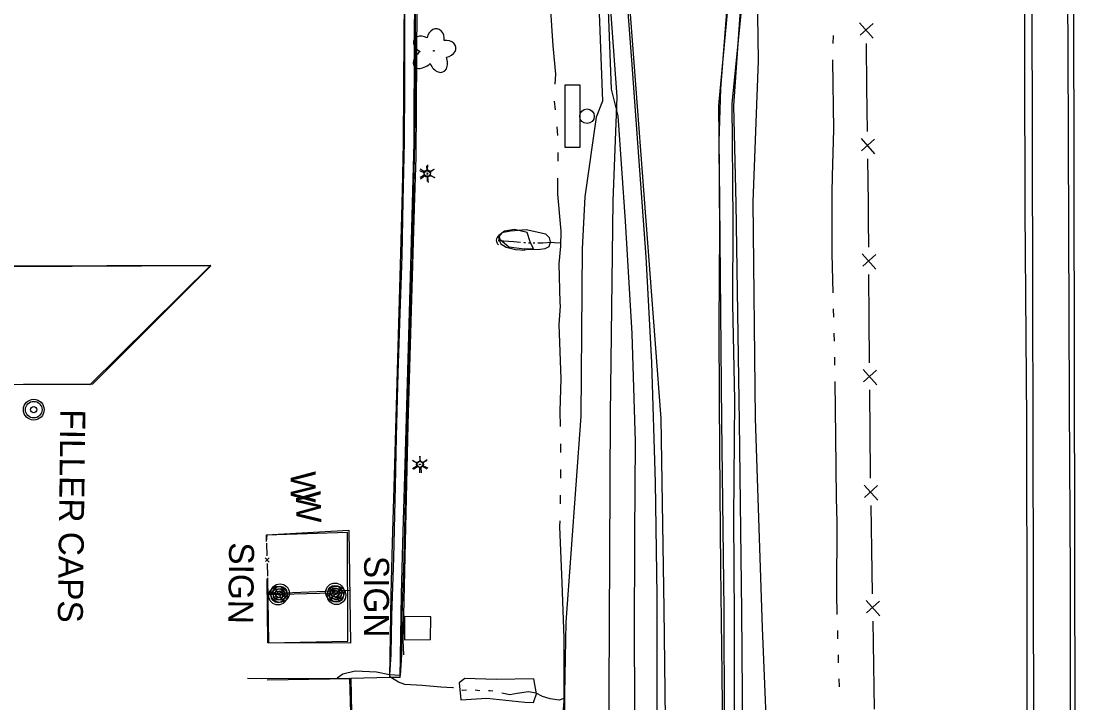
# Model space of a CAD drawing. Extents: x 588843 to 2552415, y 180129 to 269402.
# Drawn here: x 593696.8 to 593951.8, y 185185.1 to 185348.9 of the extents above; entities that cross this region are included whole.
import ezdxf

# ---------------------------------------------------------------- set-up
doc = ezdxf.new("R2010")
doc.units = 0
for name, color, linetype in [('Default', 7, 'Continuous'), ('E_BLD', 7, 'Continuous'), ('E_BLD_HvyDash', 7, 'Continuous'), ('E_DRN', 7, 'Continuous'), ('E_DRN_RipRap', 7, 'Continuous'), ('E_DWY', 7, 'Continuous'), ('E_FEN_P', 7, 'Continuous'), ('E_LAND_Vegetation', 7, 'Continuous'), ('E_LTG', 7, 'Continuous'), ('E_MISCPROP', 7, 'Continuous'), ('E_MISCPROP_Text', 7, 'Continuous'), ('E_RDWY', 7, 'Continuous'), ('E_RDWY_AsphConc', 7, 'Continuous'), ('E_RDWY_BarrierConc', 7, 'Continuous'), ('E_RDWY_C_and_G', 7, 'Continuous'), ('E_RDWY_Gravel', 7, 'Continuous'), ('E_RDWY_PavtEdge', 7, 'Continuous'), ('E_SGN', 7, 'Continuous'), ('E_SGN_Text', 7, 'Continuous'), ('E_STRUCT', 7, 'Continuous'), ('E_WAL', 7, 'Continuous'), ('E_WAL_Text', 7, 'Continuous'), ('E_WTR_P', 7, 'Continuous'), ('P_RDWY_BarrierConc', 7, 'Continuous'), ('P_RDWY_ShldPaved', 7, 'Continuous')]:
    doc.layers.add(name, color=color, linetype=linetype)

# ---------------------------------------------------------------- blocks, each defined once
blk = doc.blocks.new('FILO')
at = {"layer": 'E_MISCPROP'}
for radius in [5, 4, 1.5]:
    blk.add_circle((0, 0), radius, dxfattribs=at)
blk = doc.blocks.new('FILT')
at = {"layer": 'E_MISCPROP_Text'}
blk.add_text('FILLER CAPS', height=12, dxfattribs=at).set_placement((12, -4))
blk = doc.blocks.new('POLE')
at = {"layer": 'Default'}
for radius in [4.46, 3.35, 2.23, 1.12]:
    blk.add_circle((0, 0), radius, dxfattribs=at)
blk = doc.blocks.new('SIGN')
at = {"layer": 'Default'}
blk.add_text('SIGN', height=12, dxfattribs=at).set_placement((-18.55, -6))
blk = doc.blocks.new('LPOL')
at = {"layer": 'Default'}
for p, q in [((-4, 0), (-1.5, 0)), ((-0.75, 1.3), (-2, 3.46)), ((0.75, 1.3), (2, 3.46)), ((1.5, 0), (4, 0)), ((-2, -3.46), (-0.75, -1.3)), ((2, -3.46), (0.75, -1.3))]:
    blk.add_line(p, q, dxfattribs=at)
for radius in [1.5, 1.5, 1.5, 0.125]:
    blk.add_circle((0, 0), radius, dxfattribs=at)
blk = doc.blocks.new('W_61')
at = {"layer": 'E_WAL_Text'}
blk.add_text('W', height=12, dxfattribs=at).set_placement((-4.46, -6))
blk = doc.blocks.new('SGN_1')
at = {"layer": 'Default'}
blk.add_lwpolyline([(-3.5, -15), (-10.5, -15), (-10.5, 15), (-3.5, 15)], close=True, dxfattribs=at)
blk.add_circle((0, 0), 3.5, dxfattribs=at)
blk = doc.blocks.new('CULV2_4')
at = {"layer": 'E_DRN'}
blk.add_arc((65, 48), 80.7, 216.8699, 323.1301, dxfattribs=at)
blk = doc.blocks.new('POLE_3')
at = {"layer": 'E_MISCPROP'}
for radius in [14.6, 11, 7.32, 3.66]:
    blk.add_circle((0, 0), radius, dxfattribs=at)
blk = doc.blocks.new('LPOL_4')
at = {"layer": 'E_LTG'}
for p, q in [((-13.1, 0), (-4.9, 0)), ((-2.5, 4.3), (-6.6, 11.4)), ((2.5, 4.3), (6.6, 11.4)), ((4.9, 0), (13.1, 0)), ((-6.6, -11.4), (-2.5, -4.3)), ((6.6, -11.4), (2.5, -4.3))]:
    blk.add_line(p, q, dxfattribs=at)
for radius in [4.92, 4.92, 4.92, 0.41]:
    blk.add_circle((0, 0), radius, dxfattribs=at)
blk = doc.blocks.new('SIGN_3')
at = {"layer": 'E_SGN'}
blk.add_text('SIGN', height=39.37, dxfattribs=at).set_placement((-56.1, -19.7))
blk = doc.blocks.new('W_8_1')
at = {"layer": 'E_WAL_Text'}
blk.add_text('W', height=39.4, dxfattribs=at).set_placement((-14.6, -19.7))
blk = doc.blocks.new('DTRE_4')
at = {"layer": 'E_LAND_Vegetation'}
blk.add_circle((-0.6, 0), 0.601, dxfattribs=at)
for centre, major_axis, ratio in [((-6.1, 17.5), (4.5, -16.3), 0.782863), ((13.3, 9), (-17.3, -9.6), 0.691916), ((-19.3, 0.5), (16.2, -0.4), 0.832022), ((-8.2, -17.2), (5.9, 15.9), 0.716896), ((11.6, -12.2), (-16.4, 15), 0.560249)]:
    blk.add_ellipse(centre, major_axis=major_axis, ratio=ratio, start_param=1.570796, end_param=4.712389, dxfattribs=at)

msp = doc.modelspace()

# ---------------------------------------------------------------- linework, layer by layer
at = {"layer": 'E_BLD'}
msp.add_lwpolyline([(593595.41, 185342.82), (593542.04, 185289.64), (593742.37, 185290.28), (593713.31, 185261.53), (593514.99, 185261.87), (593447.83, 185195.35), (593433.78, 185195.34), (593433.67, 185288.83), (593458.13, 185312.89)], dxfattribs=at)
at = {"layer": 'E_BLD_HvyDash'}
msp.add_lwpolyline([(593513.7, 185260.82), (593714.03, 185261.73), (593742.37, 185290.1), (593542.12, 185289.15)], dxfattribs=at)
at = {"layer": 'E_DRN_RipRap'}
for points in [[(593818.43, 185298.09), (593815.41, 185298.81), (593812.98, 185298.45), (593811.59, 185297.38), (593811.88, 185296.54), (593814.07, 185294.67), (593817.72, 185294.22), (593819.99, 185294.22), (593819.17, 185295.85)], [(593820.03, 185190.89), (593810.98, 185190.77), (593803.43, 185190.94), (593802.1, 185189.91), (593802.48, 185185.86), (593808.76, 185186.28), (593817.87, 185185.31), (593819.94, 185185.2), (593820.71, 185187.29)]]:
    msp.add_lwpolyline(points, close=True, dxfattribs=at)
msp.add_lwpolyline([(593818.26, 185294.01), (593821.56, 185294.11), (593822.78, 185294.26), (593823.7, 185294.75), (593824.08, 185295.87), (593823.81, 185296.87), (593822.93, 185297.69), (593818.23, 185298.77), (593814.42, 185298.47), (593812.35, 185298.05), (593811.64, 185297.19), (593811.65, 185296.37), (593812.12, 185295.37), (593813.38, 185294.59), (593815.66, 185294.02), (593817.94, 185293.91)], dxfattribs=at)
at = {"layer": 'E_DWY'}
for points in [[(593779.28, 185414.41), (593780.64, 185411.67), (593783.45, 185404.25), (593785.68, 185397.13), (593787.43, 185390.2), (593788.2, 185384.9), (593788.79, 185378.59), (593788.96, 185370.88), (593789.05, 185361.06), (593788.98, 185348.55), (593788.98, 185333.57), (593788.87, 185319.82), (593788.56, 185305.76), (593788.27, 185292.48), (593787.8, 185278.7), (593787.36, 185264.28), (593786.97, 185249.03), (593786.71, 185237.17), (593786.32, 185219.98), (593785.83, 185206.1), (593785.7, 185196.77), (593785.38, 185191.85)], [(593781.51, 185415.53), (593782.94, 185412.67), (593785.82, 185405.07), (593788.08, 185397.81), (593789.89, 185390.69), (593790.68, 185385.2), (593791.29, 185378.74), (593791.46, 185370.92), (593791.55, 185361.07), (593791.48, 185348.55), (593791.48, 185333.56), (593791.37, 185319.78), (593791.06, 185305.7), (593790.76, 185292.41), (593790.29, 185278.61), (593789.86, 185264.21), (593789.47, 185248.97), (593789.21, 185237.11), (593788.82, 185219.91), (593788.33, 185206.04), (593788.2, 185196.68), (593787.88, 185191.69)], [(593791.37, 185345.7), (593791.5, 185360.24), (593791.42, 185372.16), (593790.98, 185381.83), (593790.26, 185388.49), (593789.29, 185392.53), (593787.06, 185400.28), (593783.01, 185411.71)], [(593788.87, 185345.72), (593789, 185360.24), (593788.92, 185372.09), (593788.49, 185381.64), (593787.79, 185388.06), (593786.87, 185391.89), (593784.68, 185399.51), (593780.65, 185410.88)], [(593785.39, 185191.25), (593785.75, 185211.18), (593786.05, 185223.58), (593786.54, 185239.7), (593787.08, 185259.3), (593787.56, 185276.23), (593788.06, 185293.13), (593788.48, 185308.13), (593788.74, 185319.7), (593788.87, 185345.72)], [(593787.89, 185191.21), (593788.25, 185211.13), (593788.55, 185223.52), (593789.04, 185239.63), (593789.58, 185259.23), (593790.06, 185276.16), (593790.56, 185293.06), (593790.98, 185308.07), (593791.24, 185319.67), (593791.37, 185345.7)], [(593787.88, 185191.69), (593785.38, 185191.85), (593782.22, 185192.52), (593777.11, 185192.74), (593774.09, 185191.99), (593772.73, 185191.04)], [(593787.89, 185191.21), (593785.39, 185191.25), (593776.03, 185190.97)]]:
    msp.add_lwpolyline(points, dxfattribs=at)
at = {"layer": 'E_FEN_P'}
for p, q in [((593898.37, 185348.46), (593901.63, 185344.81)), ((593901.58, 185348.33), (593898.47, 185345.52)), ((593898.71, 185320.71), (593901.97, 185317.06)), ((593901.92, 185320.58), (593898.81, 185317.76)), ((593899.01, 185292.96), (593902.25, 185289.29)), ((593902.23, 185292.82), (593899.1, 185290.01)), ((593899.22, 185265.21), (593902.46, 185261.54)), ((593902.43, 185265.06), (593899.3, 185262.26)), ((593899.45, 185237.44), (593902.73, 185233.8)), ((593902.67, 185237.32), (593899.57, 185234.49)), ((593755.48, 185219.96), (593756.43, 185218.94)), ((593756.4, 185219.94), (593755.53, 185219.12)), ((593899.93, 185209.68), (593903.21, 185206.05)), ((593903.15, 185209.57), (593900.05, 185206.74))]:
    msp.add_line(p, q, dxfattribs=at)
for points in [[(593899.91, 185343.55), (593900.04, 185332.95)], [(593900.04, 185332.95), (593900.17, 185322.36)], [(593900.25, 185315.8), (593900.38, 185305.2)], [(593900.38, 185305.2), (593900.43, 185301.11), (593900.48, 185294.6)], [(593900.53, 185288.04), (593900.61, 185277.44)], [(593900.61, 185277.44), (593900.69, 185266.85)], [(593900.74, 185260.29), (593900.82, 185249.69)], [(593900.82, 185249.69), (593900.89, 185240.29), (593900.91, 185239.09)], [(593901.02, 185232.53), (593901.2, 185221.94)], [(593755.81, 185223.45), (593755.89, 185220.44)], [(593901.2, 185221.94), (593901.39, 185211.34)], [(593755.95, 185218.57), (593756.03, 185215.56)], [(593901.5, 185204.78), (593901.68, 185194.19)], [(593901.68, 185194.19), (593901.86, 185183.59)]]:
    msp.add_lwpolyline(points, dxfattribs=at)
at = {"layer": 'E_RDWY'}
for points in [[(593875.84, 185453.5), (593875.18, 185444.55), (593873.42, 185426.77), (593871.63, 185407.61), (593869.74, 185387.1), (593868.31, 185371.28), (593866.46, 185352.19), (593864.94, 185332.65), (593864.52, 185319.97), (593864.65, 185298.49), (593864.53, 185275.87), (593864.59, 185257.56), (593864.77, 185235.68), (593864.91, 185217.64), (593865.21, 185192.03), (593865.51, 185169.15)], [(593883.34, 184797.63), (593880.29, 184822.58), (593876.81, 184852.9), (593873.76, 184879.56), (593870.15, 184910.6), (593867.01, 184938.51), (593863.39, 184971.22), (593860.52, 184996.66), (593857.95, 185023.1), (593855.61, 185048.62), (593852.95, 185083.15), (593851.06, 185119.17), (593850.2, 185152.54), (593849.72, 185184.93), (593849.66, 185210.92), (593849.31, 185238.05), (593848.37, 185266.91), (593847.03, 185292.29), (593845.07, 185319.69), (593843.62, 185339.55), (593841.62, 185365.79), (593839.25, 185395.75), (593838.48, 185404.83), (593836.91, 185426.06)]]:
    msp.add_lwpolyline(points, dxfattribs=at)
at = {"layer": 'E_RDWY_AsphConc'}
for points in [[(593880.44, 185453.26), (593877.09, 185432.82), (593874.68, 185401.65), (593869.68, 185351.53), (593868.04, 185328.52), (593868.59, 185305.06), (593869.44, 185252.63), (593869.98, 185207.15), (593870.24, 185177.47), (593870.68, 185147.16), (593871.02, 185130.16)], [(593835.51, 185420.49), (593834.36, 185418.93), (593835.27, 185400.95), (593838.25, 185354.97), (593839.96, 185330.69), (593839.05, 185305.69), (593838.39, 185254.46), (593838.17, 185204.09), (593837.95, 185155.65), (593837.92, 185121.35)]]:
    msp.add_lwpolyline(points, dxfattribs=at)
msp.add_lwpolyline([(593788.95, 185200.24), (593795.22, 185200.33), (593795.26, 185205.82), (593788.92, 185205.9)], close=True, dxfattribs=at)
at = {"layer": 'E_RDWY_BarrierConc'}
msp.add_lwpolyline([(593937.96, 185372.16), (593938.03, 185339.45), (593938.08, 185303.3), (593938.5, 185252.99), (593938.55, 185202.16), (593938.47, 185154.12), (593938.23, 185123.59), (593938.78, 185094.92), (593938.68, 185047.47)], dxfattribs=at)
at = {"layer": 'E_RDWY_C_and_G'}
msp.add_lwpolyline([(593788.78, 185196.64), (593788.64, 185200.13), (593788.81, 185206.13), (593789.8, 185251.96), (593791.36, 185304.06), (593791.76, 185316.22), (593792.01, 185352.33), (593791.93, 185366.51), (593791.98, 185372.66), (593791.74, 185378.81), (593791.74, 185378.81), (593791.28, 185384.15), (593790.58, 185389.46), (593790.58, 185389.46)], dxfattribs=at)
at = {"layer": 'E_RDWY_Gravel'}
for points in [[(593868.28, 185183.24), (593868.29, 185205.46), (593868.14, 185229.51), (593868.36, 185257.81), (593867.92, 185280.99), (593867.98, 185300.88), (593867.76, 185329.05), (593870.2, 185354), (593873.03, 185383.38), (593875.37, 185421.39), (593876.83, 185433.85), (593880.22, 185453.87)], [(593880.55, 185453.99), (593880.27, 185436.18), (593879.73, 185413.27), (593873.51, 185372.17), (593873.98, 185339.4), (593872.71, 185305.48), (593873.23, 185253.41), (593874.93, 185203.22), (593876.95, 185154.58), (593875.43, 185130.24)], [(593844.4, 185173.99), (593844.28, 185200.35), (593844.34, 185225.47), (593844.46, 185247.8), (593843.7, 185273.84), (593842.1, 185300.87), (593840.28, 185326.16), (593838.73, 185332.58), (593837.75, 185357.97), (593836.54, 185384.48), (593835.33, 185404.73), (593834.59, 185417.58), (593834.58, 185426.2)], [(593835.27, 185400.95), (593834.53, 185396.47), (593834.76, 185386.56), (593835.08, 185373.51), (593835.55, 185355.16), (593836.58, 185329.7), (593834.99, 185325.81), (593832.31, 185306.73), (593831.63, 185294.22), (593831.36, 185253.97), (593827.7, 185204.47), (593827.4, 185187.18), (593827.61, 185159.5), (593827.62, 185153.75), (593830.2, 185149.6), (593826.76, 185143.39), (593825.88, 185131.68), (593828.3, 185120.29), (593826.54, 185087.76), (593828.55, 185057.9)]]:
    msp.add_lwpolyline(points, dxfattribs=at)
at = {"layer": 'E_RDWY_PavtEdge'}
for points in [[(593875.85, 185453.59), (593873.92, 185432.86), (593870.99, 185400.68), (593866.59, 185351.79), (593864.42, 185328.6), (593864.71, 185305.3), (593865.19, 185252.78), (593865.69, 185207.57), (593865.81, 185180.99), (593866.2, 185154.42), (593866.2, 185154.42), (593866.82, 185130.11), (593866.82, 185130.11)], [(593839.4, 185400.62), (593842.88, 185354.87), (593846.48, 185307.23), (593850.58, 185253.42), (593851.31, 185207.69), (593851.9, 185154.74), (593851.9, 185154.74), (593852.41, 185121.99), (593852.41, 185121.99), (593853.62, 185093.61), (593853.62, 185093.61), (593854.67, 185076.65), (593855.94, 185059.71), (593855.94, 185059.71)]]:
    msp.add_lwpolyline(points, dxfattribs=at)
at = {"layer": 'E_SGN'}
msp.add_line((593756.39, 185211.19), (593774.53, 185211.66), dxfattribs=at)
msp.add_lwpolyline([(593756.14, 185211.36), (593775.77, 185212.17)], dxfattribs=at)
at = {"layer": 'E_STRUCT'}
msp.add_lwpolyline([(593949.5, 184809.8), (593949.49, 184844.07), (593949.38, 184874.99), (593949.34, 184910.76), (593949.25, 184952.33), (593949.24, 184977.34), (593949.2, 185005.39), (593949.13, 185032.79), (593948.99, 185077.15), (593948.89, 185110.83), (593948.85, 185154.41), (593949.04, 185179.37), (593949.06, 185215.53), (593948.81, 185257.23), (593948.62, 185298.71), (593948.49, 185342.33), (593948.21, 185388.66), (593948.33, 185405.71), (593947.89, 185415.89)], dxfattribs=at)
at = {"layer": 'E_WAL'}
for points in [[(593756.04, 185215.19), (593756.27, 185199.52), (593775.34, 185199.92), (593775.21, 185226.04), (593755.86, 185225.41), (593755.72, 185223.85)], [(593755.78, 185224.17), (593755.77, 185225.51), (593775.57, 185226.58), (593775.97, 185199.5), (593756.08, 185199.52), (593755.96, 185214.88)], [(593751.17, 185191.06), (593754.62, 185190.99), (593775.72, 185191.05), (593776.46, 185166.13), (593756.49, 185166)], [(593755.91, 185190.69), (593776.03, 185190.97), (593776.5, 185166.35), (593756.58, 185166.17)]]:
    msp.add_lwpolyline(points, dxfattribs=at)
at = {"layer": 'E_WTR_P'}
for points in [[(593823.71, 185363.59), (593823.68, 185362.86), (593823.95, 185352.65), (593824.62, 185342.95), (593825.23, 185336.17), (593825.06, 185333.77)], [(593891.98, 185345.44), (593891.92, 185343.5)], [(593891.81, 185339.64), (593891.8, 185339.36), (593892.06, 185322.9), (593891.79, 185311.63)], [(593824.94, 185329.66), (593825.14, 185327.61)], [(593825.54, 185323.51), (593825.74, 185321.46)], [(593825.8, 185317.34), (593825.79, 185315.28)], [(593825.76, 185311.16), (593825.74, 185307.36), (593826.54, 185298.42), (593826.49, 185294.8), (593826.06, 185290.58), (593826.33, 185281.34)], [(593891.79, 185311.63), (593891.69, 185307.76), (593891.65, 185293.03), (593891.92, 185283.62)], [(593811.5, 185296.21), (593815.22, 185295.99), (593816.87, 185295.82)], [(593817.62, 185295.75), (593818, 185295.71)], [(593818.76, 185295.67), (593819.14, 185295.66)], [(593819.9, 185295.65), (593820.27, 185295.64)], [(593821.03, 185295.63), (593822.23, 185295.61), (593824.33, 185295.81), (593825.03, 185295.76), (593826.5, 185295.66)], [(593826.33, 185281.34), (593826.36, 185280.46), (593826.06, 185275.99), (593826.53, 185263), (593826.28, 185255.2), (593826.38, 185251.49)], [(593892.02, 185279.75), (593892.08, 185277.82)], [(593892.19, 185273.96), (593892.24, 185272.02)], [(593892.34, 185268.16), (593892.36, 185266.23)], [(593892.4, 185262.36), (593892.53, 185249.05), (593892.76, 185234.35)], [(593826.45, 185247.37), (593826.46, 185245.31)], [(593826.47, 185241.19), (593826.47, 185239.13)], [(593826.41, 185235.01), (593826.37, 185232.95)], [(593892.76, 185234.35), (593892.85, 185228.43), (593892.79, 185211.2), (593892.92, 185206.33)], [(593826.28, 185228.83), (593826.25, 185227.49), (593826.77, 185213.98), (593827.24, 185200.64), (593827.24, 185198.97)], [(593893.03, 185202.47), (593893.08, 185200.53)], [(593827.24, 185198.97), (593827.27, 185187.73), (593827.24, 185185.54), (593826.81, 185179.57), (593826.86, 185173.47), (593827.24, 185169.13)], [(593893.19, 185196.67), (593893.24, 185194.74)], [(593800.69, 185188.74), (593800.59, 185188.77), (593797.7, 185188.86), (593793.18, 185189.32), (593789.04, 185189.52), (593787.48, 185190.13), (593785.43, 185191.35)], [(593893.35, 185190.88), (593893.45, 185188.95)], [(593803.83, 185188.14), (593802.8, 185188.12), (593802.76, 185188.13)], [(593807.03, 185188.05), (593805.97, 185188.15)], [(593810.22, 185187.9), (593809.58, 185188.02), (593809.16, 185187.99)], [(593827.25, 185186.19), (593826.12, 185185.8), (593823.99, 185186.07), (593822.12, 185186.67), (593820.61, 185187.42), (593818.78, 185187.81), (593816.04, 185187.39), (593814.25, 185187.04), (593812.31, 185187.49)]]:
    msp.add_lwpolyline(points, dxfattribs=at)
at = {"layer": 'P_RDWY_BarrierConc'}
msp.add_line((593941.13, 184768.81), (593939.74, 185387.02), dxfattribs=at)
at = {"layer": 'P_RDWY_ShldPaved'}
msp.add_line((593951.77, 184483.94), (593949.78, 185371.03), dxfattribs=at)

# ---------------------------------------------------------------- block references
at = {"layer": 'E_DRN', "xscale": 0.017300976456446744, "yscale": 0.017300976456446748, "rotation": -93.43141079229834}
msp.add_blockref('CULV2_4', (593811.65, 185297.41), dxfattribs=at)
at = {"layer": 'E_LAND_Vegetation', "xscale": 0.1524003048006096, "yscale": 0.1524003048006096, "rotation": -97.36026881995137}
msp.add_blockref('DTRE_4', (593795.98, 185341.68), dxfattribs=at)
at = {"layer": 'E_LTG'}
for name, p, xscale, yscale, rotation in [('LPOL_4', (593794.41, 185312.15), 0.1524003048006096, 0.15240030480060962, -84.36014555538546), ('LPOL', (593794.42, 185312.38), 0.5000000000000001, 0.5, -90.72490345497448), ('LPOL', (593792.59, 185242.4), 0.5000000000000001, 0.5, -90.72490345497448), ('LPOL_4', (593792.77, 185242.41), 0.1524003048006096, 0.15240030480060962, -84.36014555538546)]:
    msp.add_blockref(name, p, dxfattribs=dict(at, xscale=xscale, yscale=yscale, rotation=rotation))
at = {"layer": 'E_MISCPROP'}
for name, p, xscale, yscale, rotation in [('FILO', (593699.82, 185255.56), 0.5000000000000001, 0.5, -90.72490345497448), ('POLE_3', (593758.54, 185210.87), 0.1524003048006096, 0.15240030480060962, -84.36014555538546), ('POLE', (593759.03, 185211.48), 0.5000000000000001, 0.5, -90.72490345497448), ('POLE', (593772.22, 185211.67), 0.5000000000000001, 0.5, -90.72490345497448), ('POLE_3', (593772.6, 185210.96), 0.1524003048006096, 0.15240030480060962, -84.36014555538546)]:
    msp.add_blockref(name, p, dxfattribs=dict(at, xscale=xscale, yscale=yscale, rotation=rotation))
at = {"layer": 'E_MISCPROP_Text', "xscale": 0.5000000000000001, "yscale": 0.5, "rotation": -90.72490345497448}
msp.add_blockref('FILT', (593708.32, 185261.66), dxfattribs=at)
at = {"layer": 'E_SGN', "xscale": 0.5, "yscale": 0.5}
msp.add_blockref('SGN_1', (593832.83, 185326.06), dxfattribs=at)
at = {"layer": 'E_SGN_Text'}
for name, p, xscale, yscale, rotation in [('SIGN', (593749.69, 185214.42), 0.5000000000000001, 0.5, -90.72490345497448), ('SIGN_3', (593782.24, 185211.89), 0.1524003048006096, 0.1524003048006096, -90.18446500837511)]:
    msp.add_blockref(name, p, dxfattribs=dict(at, xscale=xscale, yscale=yscale, rotation=rotation))
at = {"layer": 'E_WAL_Text'}
for name, p, xscale, yscale, rotation in [('W_8_1', (593764.62, 185238.59), 0.1524003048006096, 0.15240030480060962, -90.23323317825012), ('W_61', (593765.86, 185233.77), 0.49999999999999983, 0.4999999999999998, -88.93139815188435)]:
    msp.add_blockref(name, p, dxfattribs=dict(at, xscale=xscale, yscale=yscale, rotation=rotation))

doc.saveas('drawing.dxf')
